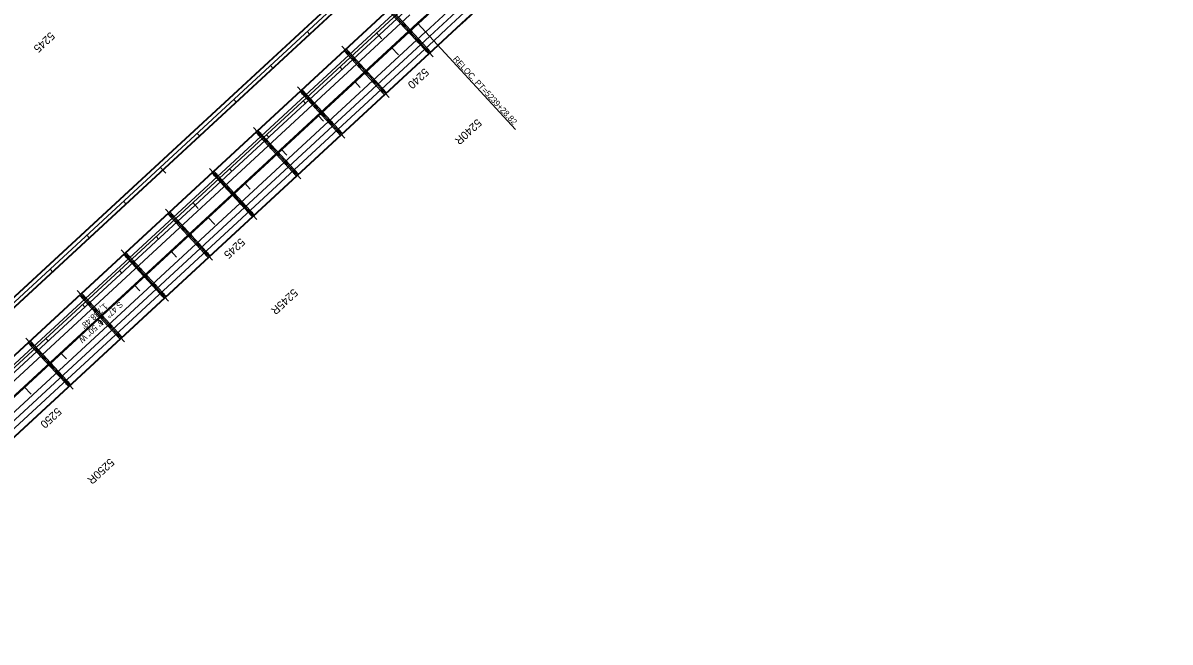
# Model space of a CAD drawing. Extents: x 2160877 to 2175861, y 601747 to 617724.
# Drawn here: x 2166538 to 2168832, y 607845 to 609082 of the extents above; entities that cross this region are included whole.
import ezdxf

# ---------------------------------------------------------------- set-up
doc = ezdxf.new("R2010")
doc.units = 0
for name, color, linetype in [('BR_CENTER LINES', 7, 'Continuous'), ('BR_CONCRETE', 7, 'Continuous'), ('RD_HC_Cl', 7, 'Continuous'), ('RD_HC_CL_Rel', 7, 'Continuous'), ('RD_HC_Data_Rel', 7, 'Continuous'), ('RD_HC_Data_Tic', 7, 'Continuous'), ('RD_HC_Data_Tic_Rel', 7, 'Continuous'), ('RD_HC_TX_Rel_Sta50', 7, 'Continuous'), ('RD_HC_TX_Rel_StaOther', 7, 'Continuous'), ('RD_HC_TX_StaOther', 7, 'Continuous'), ('RD_PD_Final_LnLine', 7, 'Continuous'), ('RD_PD_MedBWall', 7, 'Continuous')]:
    doc.layers.add(name, color=color, linetype=linetype)

msp = doc.modelspace()

# ---------------------------------------------------------------- linework, layer by layer
at = {"layer": 'BR_CENTER LINES'}
for p, q in [((2167263.7, 609117.2), (2167358.3, 609014.8)), ((2167175.6, 609035.8), (2167270.1, 608933.4)), ((2167087.4, 608954.4), (2167181.9, 608852)), ((2166999.2, 608873), (2167093.8, 608770.6)), ((2166911.1, 608791.6), (2167005.6, 608689.2)), ((2166822.9, 608710.2), (2166917.4, 608607.8)), ((2166734.8, 608628.7), (2166829.3, 608526.4)), ((2166646.6, 608547.3), (2166741.1, 608445)), ((2166543.7, 608452.4), (2166638.3, 608350))]:
    msp.add_line(p, q, dxfattribs=at)
at = {"layer": 'BR_CONCRETE'}
for p, q in [((2167286.8, 609125.7), (2166009.5, 607946.3)), ((2167286.8, 609125.6), (2166009.6, 607946.2)), ((2167287.5, 609124.9), (2166010.3, 607945.5)), ((2167326.9, 609082.3), (2166049.6, 607902.9)), ((2167328.4, 609080.5), (2166051.2, 607901.1)), ((2167367.8, 609037.9), (2166090.6, 607858.5)), ((2167368.5, 609037.2), (2166091.2, 607857.8)), ((2167368.6, 609037.1), (2166091.3, 607857.7)), ((2167093.7, 608947.6), (2167175.7, 608858.8)), ((2167005.5, 608866.2), (2167087.5, 608777.4)), ((2166917.3, 608784.8), (2166999.4, 608696)), ((2166829.2, 608703.4), (2166911.2, 608614.6)), ((2166741, 608622), (2166823, 608533.1)), ((2166652.8, 608540.6), (2166734.9, 608451.7)), ((2166550, 608445.6), (2166632, 608356.8))]:
    msp.add_line(p, q, dxfattribs=at)
for points in [[(2167272.5, 609111.7), (2167268.5, 609108), (2167349.5, 609020.3), (2167353.5, 609024)], [(2167184.4, 609030.3), (2167180.3, 609026.6), (2167261.3, 608938.9), (2167265.3, 608942.6)], [(2167096.2, 608948.9), (2167092.2, 608945.2), (2167173.1, 608857.5), (2167177.2, 608861.2)], [(2167008.1, 608867.5), (2167004, 608863.8), (2167085, 608776.1), (2167089, 608779.8)], [(2166919.9, 608786.1), (2166915.8, 608782.4), (2166996.8, 608694.7), (2167000.8, 608698.4)], [(2166831.7, 608704.7), (2166827.7, 608700.9), (2166908.6, 608613.3), (2166912.7, 608617)], [(2166743.6, 608623.3), (2166739.5, 608619.5), (2166820.5, 608531.9), (2166824.5, 608535.6)], [(2166655.4, 608541.9), (2166651.4, 608538.1), (2166732.3, 608450.5), (2166736.4, 608454.2)], [(2166552.5, 608446.9), (2166548.5, 608443.1), (2166629.5, 608355.5), (2166633.5, 608359.2)]]:
    msp.add_lwpolyline(points, close=True, dxfattribs=at)
for centre, radius in [((2167300.2, 609077.7), 3), ((2167300.2, 609077.7), 2), ((2167312.6, 609064.2), 3), ((2167312.6, 609064.2), 2), ((2167329.6, 609045.9), 3), ((2167329.6, 609045.9), 2), ((2167187.2, 609023.2), 3), ((2167187.2, 609023.2), 2), ((2167346.6, 609027.5), 3), ((2167346.6, 609027.5), 2), ((2167199.6, 609009.8), 3), ((2167199.6, 609009.8), 2), ((2167212, 608996.3), 3), ((2167212, 608996.3), 2), ((2167224.5, 608982.8), 3), ((2167224.5, 608982.8), 2), ((2167241.4, 608964.5), 3), ((2167241.4, 608964.5), 2), ((2167258.4, 608946.1), 3), ((2167258.4, 608946.1), 2), ((2167099, 608941.8), 3), ((2167099, 608941.8), 2), ((2167111.4, 608928.4), 3), ((2167111.4, 608928.4), 2), ((2167123.9, 608914.9), 3), ((2167123.9, 608914.9), 2), ((2167136.3, 608901.4), 3), ((2167136.3, 608901.4), 2), ((2167153.3, 608883.1), 3), ((2167153.3, 608883.1), 2), ((2167010.8, 608860.4), 3), ((2167010.8, 608860.4), 2), ((2167170.2, 608864.7), 3), ((2167170.2, 608864.7), 2), ((2167023.3, 608847), 3), ((2167023.3, 608847), 2), ((2167035.7, 608833.5), 3), ((2167035.7, 608833.5), 2), ((2167048.1, 608820), 3), ((2167048.1, 608820), 2), ((2167065.1, 608801.7), 3), ((2167065.1, 608801.7), 2), ((2167082.1, 608783.3), 3), ((2166922.7, 608779), 3), ((2166922.7, 608779), 2), ((2166935.1, 608765.5), 3), ((2166935.1, 608765.5), 2), ((2167082.1, 608783.3), 2), ((2166947.5, 608752.1), 3), ((2166947.5, 608752.1), 2), ((2166960, 608738.6), 3), ((2166960, 608738.6), 2), ((2166976.9, 608720.2), 3), ((2166976.9, 608720.2), 2), ((2166834.5, 608697.6), 3), ((2166834.5, 608697.6), 2), ((2166993.9, 608701.9), 3), ((2166993.9, 608701.9), 2), ((2166846.9, 608684.1), 3), ((2166846.9, 608684.1), 2), ((2166859.4, 608670.7), 3), ((2166859.4, 608670.7), 2), ((2166871.8, 608657.2), 3), ((2166871.8, 608657.2), 2), ((2166888.8, 608638.8), 3), ((2166888.8, 608638.8), 2), ((2166746.3, 608616.2), 3), ((2166746.3, 608616.2), 2), ((2166758.8, 608602.7), 3), ((2166758.8, 608602.7), 2), ((2166905.7, 608620.5), 3), ((2166905.7, 608620.5), 2), ((2166771.2, 608589.3), 3), ((2166771.2, 608589.3), 2), ((2166783.7, 608575.8), 3), ((2166783.7, 608575.8), 2), ((2166800.6, 608557.4), 3), ((2166800.6, 608557.4), 2), ((2166658.2, 608534.8), 3), ((2166658.2, 608534.8), 2), ((2166817.6, 608539.1), 3), ((2166817.6, 608539.1), 2), ((2166670.6, 608521.3), 3), ((2166670.6, 608521.3), 2), ((2166683.1, 608507.9), 3), ((2166683.1, 608507.9), 2), ((2166695.5, 608494.4), 3), ((2166695.5, 608494.4), 2), ((2166712.5, 608476), 3), ((2166712.5, 608476), 2), ((2166555.3, 608439.8), 3), ((2166729.4, 608457.6), 3), ((2166729.4, 608457.6), 2), ((2166555.3, 608439.8), 2), ((2166567.8, 608426.3), 3), ((2166567.8, 608426.3), 2), ((2166580.2, 608412.9), 3), ((2166580.2, 608412.9), 2), ((2166592.6, 608399.4), 3), ((2166592.6, 608399.4), 2), ((2166609.6, 608381), 3), ((2166609.6, 608381), 2), ((2166626.6, 608362.7), 3), ((2166626.6, 608362.7), 2)]:
    msp.add_circle(centre, radius, dxfattribs=at)
for radius in [72498.8, 72501.2, 72559.2, 72560.2, 72560.3]:
    msp.add_arc((2118143, 662346), radius, 312.719474, 314.001574, dxfattribs=at)
at = {"layer": 'RD_HC_Cl'}
for p, q in [((2172207.3, 613775.1), (2163672.2, 605893.8)), ((2172272.5, 613704.6), (2163737.4, 605823.3))]:
    msp.add_line(p, q, dxfattribs=at)
at = {"layer": 'RD_HC_CL_Rel'}
msp.add_line((2167327.7, 609081.4), (2166050.4, 607902), dxfattribs=at)
msp.add_arc((2118143, 662346), 72500, 312.719474, 314.517591, dxfattribs=at)
at = {"layer": 'RD_HC_Data_Rel'}
msp.add_line((2167327.7, 609081.4), (2167523.3, 608869.6), dxfattribs=at)
at = {"layer": 'RD_HC_Data_Tic'}
for p, q in [((2167106.6, 609065.1), (2167112, 609059.2)), ((2167245.2, 609062.4), (2167256, 609050.6)), ((2167033.1, 608997.2), (2167038.5, 608991.4)), ((2167171.7, 608994.6), (2167177.1, 608988.7)), ((2166959.6, 608929.4), (2166965.1, 608923.5)), ((2167098.2, 608926.7), (2167103.6, 608920.8)), ((2166886.2, 608861.6), (2166891.6, 608855.7)), ((2167024.8, 608858.9), (2167030.2, 608853)), ((2166812.7, 608793.7), (2166823.5, 608782)), ((2166951.3, 608791), (2166956.7, 608785.2)), ((2166739.2, 608725.9), (2166744.6, 608720)), ((2166877.8, 608723.2), (2166888.7, 608711.4)), ((2166665.7, 608658), (2166671.2, 608652.2)), ((2166804.3, 608655.3), (2166809.8, 608649.5)), ((2166592.3, 608590.2), (2166597.7, 608584.3)), ((2166730.9, 608587.5), (2166736.3, 608581.6)), ((2166657.4, 608519.7), (2166662.8, 608513.8)), ((2166583.9, 608451.8), (2166589.4, 608445.9))]:
    msp.add_line(p, q, dxfattribs=at)
at = {"layer": 'RD_HC_Data_Tic_Rel'}
for p, q in [((2167275.4, 609033.1), (2167288.9, 609018.4)), ((2167201.9, 608965.3), (2167212.7, 608953.5)), ((2167128.4, 608897.4), (2167139.3, 608885.7)), ((2167055, 608829.6), (2167065.8, 608817.8)), ((2166981.5, 608761.8), (2166992.3, 608750)), ((2166908, 608693.9), (2166921.6, 608679.2)), ((2166834.6, 608626.1), (2166845.4, 608614.3)), ((2166761.1, 608558.2), (2166771.9, 608546.5)), ((2166687.6, 608490.4), (2166698.5, 608478.6)), ((2166614.1, 608422.5), (2166625, 608410.8)), ((2166540.7, 608354.7), (2166554.2, 608340))]:
    msp.add_line(p, q, dxfattribs=at)
at = {"layer": 'RD_PD_Final_LnLine'}
for p, q in [((2166018.4, 607936.7), (2167295.7, 609116.1)), ((2166026.6, 607927.8), (2167303.8, 609107.2)), ((2166034.7, 607919), (2167311.9, 609098.4)), ((2166049.6, 607902.9), (2167326.9, 609082.3)), ((2166051.2, 607901.1), (2167328.4, 609080.5)), ((2166066.1, 607885), (2167343.4, 609064.4)), ((2166074.3, 607876.2), (2167351.5, 609055.6)), ((2166082.4, 607867.4), (2167359.7, 609046.8))]:
    msp.add_line(p, q, dxfattribs=at)
for radius in [72501.2, 72523.2, 72535.2, 72547.2]:
    msp.add_arc((2118143, 662346), radius, 312.719474, 314.517591, dxfattribs=at)
at = {"layer": 'RD_PD_MedBWall'}
for p, q in [((2169697.9, 611469.1), (2165055.7, 607182.5)), ((2169698.6, 611468.4), (2165056.4, 607181.7)), ((2169708.3, 611458.3), (2165065.8, 607171.5)), ((2169684.4, 611434.9), (2165066.5, 607170.7))]:
    msp.add_line(p, q, dxfattribs=at)

# ---------------------------------------------------------------- texts
at = {"layer": 'RD_HC_Data_Rel'}
msp.add_text('RELOC. PT=5239+28.82', height=12, rotation=312.7195, dxfattribs=at).set_placement((2167397, 609009.3))
at = {"layer": 'RD_HC_TX_Rel_Sta50'}
for s, p in [('5240R', (2167446.5, 608891.7)), ('5245R', (2167078.9, 608552.2)), ('5250R', (2166711.8, 608213.2))]:
    msp.add_text(s, height=16, rotation=222.7195, dxfattribs=at).set_placement(p)
at = {"layer": 'RD_HC_TX_Rel_StaOther'}
for s, p in [('S 47%%d 16\' 50" W', (2166731.3, 608526.6)), ("1,738.48'", (2166700.9, 608523))]:
    msp.add_text(s, height=12, rotation=222.7195, dxfattribs=at).set_placement(p)
at = {"layer": 'RD_HC_TX_StaOther'}
for s, p in [('5245', (2166592.8, 609065.5)), ('5240', (2167341, 608993)), ('5245', (2166973.3, 608653.5)), ('5250', (2166606.3, 608314.6))]:
    msp.add_text(s, height=16, rotation=222.7195, dxfattribs=at).set_placement(p)

doc.saveas('drawing.dxf')
